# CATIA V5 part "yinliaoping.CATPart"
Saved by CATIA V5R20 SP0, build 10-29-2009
Part number: Part1
Material "DS Light Blue": density 7860 kg/m3, Young's modulus 2e+11 Pa, Poisson ratio 0.266
Bounding box of the stored display mesh (mm): x -25 to 25, y -25 to 477.831, z 0 to 569.591
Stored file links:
  C:\Users\Machenike\Desktop\zuoye\yinliaoping.CATPart
  D:\CATIAR20\win_b64\startup\materials\Catalog.CATMaterial
  D:\CATIAR20\win_b64\startup\materials\floor.jpg
  D:\CATIAR20\win_b64\startup\materials\blue_fabric_02.jpg
  D:\CATIAR20\win_b64\startup\materials\blue_env_512x512.jpg
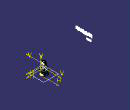
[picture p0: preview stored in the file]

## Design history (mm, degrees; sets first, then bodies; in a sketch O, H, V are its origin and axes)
Set1
  Sketch1 on xy-plane, origin (0, 0, 0), H (1, 0, 0), V (0, 1, 0)
    line L1 (25, 25) -> (25, -25)
    line L2 (25, -25) -> (-25, -25)
    line L3 (-25, -25) -> (-25, 25)
    line L4 (-25, 25) -> (25, 25)
    length L1 = 50
    length L4 = 50
    vertical: L1 V, L3 V
    horizontal: L2 H, L4 H
    equidistance: L1 L3 O, L2 L4 O
  Sketch2 on face of Pad1 from Sketch1.L1, origin (25, 0, 0), H (0, 1, 0), V (0, 0, 1)
    spline S1 through (-37.2016, 14.3943) (-10.1792, 27.927) (7.291, 18.0281) (38.3353, 27.927)
  Extrude1: Element1 Sketch2, Lim1 53, Lim2 53
Body1 (main body), material "DS Light Blue"
  Pad1: profile Sketch1, direction (0, 0, 1), length 50
  Fillet1: on edge [face of Pad1 from Sketch1.L4 | face of Pad1 from Sketch1.L1]; edge [face of Pad1 from Sketch1.L1 | face of Pad1 from Sketch1.L2]; edge [face of Pad1 from Sketch1.L2 | face of Pad1 from Sketch1.L3]; edge [face of Pad1 from Sketch1.L3 | face of Pad1 from Sketch1.L4]
  Plane1: type Offset, RefPlane xy-plane, Offset 80
  Sketch3 on Plane1, origin (0, 0, 80), H (1, 0, 0), V (0, 1, 0)
    circle A1 centre (0, 0) radius 15
    radius A1 = 15
  Pad2: profile Sketch3, direction (0, 0, 1), length 20
  Sketch4 on end face of Pad1, origin (0, 0, 50), H (1, 0, 0), V (0, 1, 0)
    point P1 (25, 0)
    distance P1 O = 25
    coincidence: P1 H
  Sketch5 on start face of Pad2, origin (0, 0, 80), H (1, 0, 0), V (0, -1, 0)
    point P1 (15, 0)
    distance P1 O = 15
    coincidence: P1 H
  Sketch6 on end face of Pad1, origin (0, 0, 50), H (1, 0, 0), V (0, 1, 0)
    point P1 (0, 0)
    point P2 (0, 25)
    distance P2 P1 = 25
    coincidence: P1 O, P2 V
  Loft1: solid, Sections ({boundary Boundary {extract ExtractElem end face of Pad1}}; {boundary Boundary {extract ExtractElem start face of Pad2}}), StartFace end face of Pad1, EndFace start face of Pad2
  MultiSel1: CommonCtxFeats ({extract ExtractElem face of Pad1 from Sketch1.L2}; {extract ExtractElem face of Fillet1}; {extract ExtractElem face of Pad1 from Sketch1.L1}; {extract ExtractElem face of Fillet1}; {extract ExtractElem face of Pad1 from Sketch1.L4}; {extract ExtractElem face of Fillet1}; {extract ExtractElem face of Pad1 from Sketch1.L3}; {extract ExtractElem face of Fillet1})
  Sketch7 on face of Pad1 from Sketch1.L3, origin (-25, 0, 0), H (0, -1, 0), V (0, 0, 1)
    spline S1 through (-38.912, 44.8124) (-17.3383, 31.002) (-3.0315, 36.8884) (13.7046, 42.9633) (37.1637, 32.134) (41.9327, 26.2476)
  Extrude2: Element1 Sketch7, Lim1 55, Lim2 55
  MultiSel2: CommonCtxFeats ({extract ExtractElem face of Pad1 from Sketch1.L2}; {extract ExtractElem face of Fillet1}; {extract ExtractElem face of Pad1 from Sketch1.L1}; {extract ExtractElem face of Fillet1}; {extract ExtractElem face of Pad1 from Sketch1.L4}; {extract ExtractElem face of Fillet1}; {extract ExtractElem face of Pad1 from Sketch1.L3}; {extract ExtractElem face of Fillet1})
  Join1: Elements ({intersect ToIntersect1 {extract ExtractElem face of Pad1 from Sketch1.L2}, ToIntersect2 Extrude2}; {intersect ToIntersect1 {extract ExtractElem face of Pad1 from Sketch1.L1}, ToIntersect2 Extrude2}; {intersect ToIntersect1 {extract ExtractElem face of Fillet1}, ToIntersect2 Extrude2}; {intersect ToIntersect1 {extract ExtractElem face of Pad1 from Sketch1.L4}, ToIntersect2 Extrude2}; {intersect ToIntersect1 {extract ExtractElem face of Fillet1}, ToIntersect2 Extrude2}; {intersect ToIntersect1 {extract ExtractElem face of Pad1 from Sketch1.L3}, ToIntersect2 Extrude2}; {intersect ToIntersect1 {extract ExtractElem face of Fillet1}, ToIntersect2 Extrude2}; {intersect ToIntersect1 {extract ExtractElem face of Fillet1}, ToIntersect2 Extrude2})
  Join2: Elements ({intersect ToIntersect1 {extract ExtractElem face of Pad1 from Sketch1.L1}, ToIntersect2 Extrude1}; {intersect ToIntersect1 {extract ExtractElem face of Fillet1}, ToIntersect2 Extrude1}; {intersect ToIntersect1 {extract ExtractElem face of Pad1 from Sketch1.L4}, ToIntersect2 Extrude1}; {intersect ToIntersect1 {extract ExtractElem face of Fillet1}, ToIntersect2 Extrude1}; {intersect ToIntersect1 {extract ExtractElem face of Pad1 from Sketch1.L3}, ToIntersect2 Extrude1}; {intersect ToIntersect1 {extract ExtractElem face of Fillet1}, ToIntersect2 Extrude1}; {intersect ToIntersect1 {extract ExtractElem face of Pad1 from Sketch1.L2}, ToIntersect2 Extrude1}; {intersect ToIntersect1 {extract ExtractElem face of Fillet1}, ToIntersect2 Extrude1})
  Plane2: type Normal, Curve Join1, RefPoint vertex [face of MultiSel2 | face of MultiSel2]
  Circle1: type CtrRad, Start 0, End 180, Center vertex [face of MultiSel2 | face of MultiSel2], Support Plane2, Radius 1, FirstDirection (0, 1, 0)
  Plane3: type Normal, Curve Join2, RefPoint vertex [face of MultiSel1 | face of MultiSel1]
  Circle2: type CtrRad, Start 0, End 180, Center vertex [face of MultiSel1 | face of MultiSel1], Support Plane3, Radius 1, FirstDirection (0, -1, 0)
  Slot1: profile Circle1, centre curve Join1
  Slot2: profile Circle2, centre curve Join2
  Shell1: IntOffset 1, Face end face of Pad2, ExtOffset 0
  Point1: type OnSurface, Support face of Pad2 from Sketch3.A1, Length 8, Direction (-0.0374, 0.0003, -0.9993)
  Helix1: Direction Z axis, RefPoint Point1, Pitch 3, Height 16, TaperAngle 0
  Point2: type OnCurve, Support Helix1, Length 5
  Point3: type OnCurve, Support Helix1, RefPoint vertex of Helix1, Length -5
  Line1: type PtDir, RefPoint vertex of Helix1, Direction (1, 0, 0), Start 0, End 5
  Line2: type PtDir, RefPoint Point1, Direction (0, 1, 0), Start 0, End 5
  Connect1: Curve1 Line1, Point1 vertex of Line1, Tension1 1, Curve2 Helix1, Point2 Point3, Tension2 1
  Connect2: Curve1 Line2, Point1 vertex of Line2, Tension1 1, Curve2 Connect1, Point2 Point2, Tension2 1
  Plane4: type Normal, Curve Connect2, RefPoint vertex of Connect1
  Circle3: type CtrRad, Start 0, End 180, Center vertex of Connect1, Support Plane4, Radius 1, FirstDirection (0, 1, 0)
  Rib1: profile Circle3, centre curve Connect2
  Body2
    Sketch8 on {extract ExtractElem start face of Pad2}, origin (0, 0, 80), H (1, 0, 0), V (0, 1, 0)
      circle A1 centre (0, 0) radius 14
      radius A1 = 14
    Pad3: profile Sketch8, direction (0, 0, 1), length 20
  Remove1: tool Body2
Body3
  Sketch9 on face of Pad1 from Sketch1.L1, origin (25, 0, 0), H (0, 1, 0), V (0, 0, 1)
    polyline C1
    polyline C2
    polyline C3
    polyline C4
    polyline C5
    polyline C6
    polyline C7
    polyline C8
    polyline C9
    polyline C10
    polyline C11
    polyline C12
    polyline C13
    polyline C14
    polyline C15
    polyline C16
    polyline C17
    polyline C18
    polyline C19
    polyline C20
    polyline C21
    polyline C22
    polyline C23
    polyline C24
    polyline C25
    polyline C26
    polyline C27
    polyline C28
    polyline C29
    polyline C30
    polyline C31
    polyline C32
    polyline C33
  Sketch10 on face of Pad1 from Sketch1.L1, origin (25, 0, 0), H (0, 1, 0), V (0, 0, 1)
